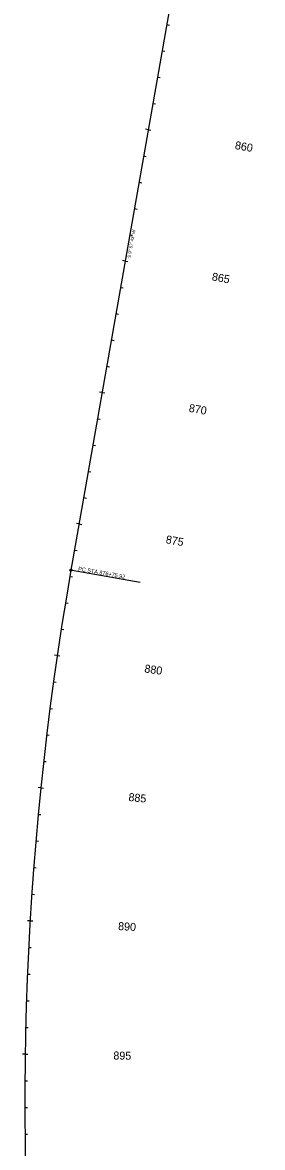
# Model space of a CAD drawing. Extents: x 2820825 to 2825694, y 116785 to 142398.
# Drawn here: x 2820825 to 2821726, y 129646 to 133862 of the extents above; entities that cross this region are included whole.
import ezdxf

# ---------------------------------------------------------------- set-up
doc = ezdxf.new("R2010")
doc.units = 0
for name, color, linetype in [('Default', 7, 'Continuous'), ('Roadway-Centerline main', 7, 'Continuous'), ('Roadway-Curve pc pt', 7, 'Continuous'), ('Text-Alignment info', 7, 'Continuous')]:
    doc.layers.add(name, color=color, linetype=linetype)

msp = doc.modelspace()

# ---------------------------------------------------------------- linework, layer by layer
at = {"layer": 'Default'}
msp.add_line((2821447.5, 134317.2), (2821007.1, 131809.7), dxfattribs=at)
msp.add_arc((2832333.7, 129820.2), 11500, 170.03806, 202.7163, dxfattribs=at)
at = {"layer": 'Roadway-Centerline main'}
for p, q in [((2821447.5, 134317.2), (2821007.1, 131809.7)), ((2821366.2, 133854.3), (2821376.1, 133852.6)), ((2821348.9, 133755.8), (2821358.8, 133754.1)), ((2821331.6, 133657.3), (2821341.5, 133655.6)), ((2821314.3, 133558.8), (2821324.2, 133557.1)), ((2821297, 133460.3), (2821287.2, 133462.1)), ((2821297, 133460.3), (2821306.9, 133458.6)), ((2821279.7, 133361.8), (2821289.6, 133360.1)), ((2821262.4, 133263.3), (2821272.3, 133261.6)), ((2821245.1, 133164.8), (2821255, 133163.1)), ((2821227.8, 133066.4), (2821237.7, 133064.6)), ((2821210.5, 132967.9), (2821200.7, 132969.6)), ((2821210.5, 132967.9), (2821220.4, 132966.1)), ((2821193.2, 132869.4), (2821203.1, 132867.6)), ((2821175.9, 132770.9), (2821185.8, 132769.2)), ((2821158.6, 132672.4), (2821168.5, 132670.7)), ((2821141.3, 132573.9), (2821151.2, 132572.2)), ((2821124, 132475.4), (2821114.2, 132477.1)), ((2821124, 132475.4), (2821133.9, 132473.7)), ((2821106.7, 132376.9), (2821116.6, 132375.2)), ((2821089.4, 132278.4), (2821099.3, 132276.7)), ((2821072.1, 132179.9), (2821082, 132178.2)), ((2821054.8, 132081.4), (2821064.7, 132079.7)), ((2821037.5, 131982.9), (2821027.7, 131984.7)), ((2821037.5, 131982.9), (2821047.4, 131981.2)), ((2821020.2, 131884.5), (2821030.1, 131882.7)), ((2821002.9, 131786), (2821012.8, 131784.2)), ((2820986.3, 131687.4), (2820996.1, 131685.7)), ((2820970.5, 131588.6), (2820980.3, 131587.1)), ((2820955.5, 131489.7), (2820945.6, 131491.2)), ((2820955.5, 131489.7), (2820965.4, 131488.3)), ((2820941.4, 131390.7), (2820951.3, 131389.4)), ((2820928.2, 131291.6), (2820938.1, 131290.3)), ((2820915.8, 131192.4), (2820925.8, 131191.2)), ((2820904.3, 131093), (2820914.3, 131091.9)), ((2820893.7, 130993.6), (2820883.8, 130994.6)), ((2820893.7, 130993.6), (2820903.7, 130992.6)), ((2820883.9, 130894.1), (2820893.9, 130893.2)), ((2820875, 130794.5), (2820885, 130793.6)), ((2820867, 130694.8), (2820877, 130694)), ((2820859.8, 130595.1), (2820869.8, 130594.4)), ((2820853.5, 130495.3), (2820843.5, 130495.9)), ((2820853.5, 130495.3), (2820863.5, 130494.7)), ((2820848.1, 130395.4), (2820858.1, 130394.9)), ((2820843.5, 130295.5), (2820853.5, 130295.1)), ((2820839.8, 130195.6), (2820849.8, 130195.3)), ((2820837, 130095.6), (2820847, 130095.4)), ((2820835, 129995.6), (2820825, 129995.8)), ((2820835, 129995.6), (2820845, 129995.5)), ((2820833.9, 129895.7), (2820843.9, 129895.6)), ((2820833.7, 129795.7), (2820843.7, 129795.7)), ((2820834.4, 129695.7), (2820844.4, 129695.8))]:
    msp.add_line(p, q, dxfattribs=at)
msp.add_arc((2832333.7, 129820.2), 11500, 170.03806, 202.7163, dxfattribs=at)
at = {"layer": 'Roadway-Curve pc pt'}
msp.add_line((2821011, 131809), (2821266.9, 131764), dxfattribs=at)
msp.add_circle((2821007.1, 131809.7), 4, dxfattribs=at)

# ---------------------------------------------------------------- texts
at = {"layer": 'Roadway-Centerline main'}
for s, rotation, p in [(' 860', 350.0381, (2821609.6, 133390.2)), (' 865', 350.0381, (2821523.1, 132897.7)), (' 870', 350.0381, (2821436.6, 132405.3)), (' 875', 350.0381, (2821350.1, 131912.8)), (' 880', 351.6527, (2821270, 131428.4)), (' 885', 354.1438, (2821210.5, 130946)), (' 890', 356.635, (2821172.1, 130461.5)), (' 895', 359.1261, (2821154.8, 129975.8))]:
    msp.add_text(s, height=30, rotation=rotation, dxfattribs=at).set_placement(p)
at = {"layer": 'Roadway-Curve pc pt'}
msp.add_text('PC STA 876+75.92', height=15, rotation=350.0381, dxfattribs=at).set_placement((2821033.2, 131808.1))
at = {"layer": 'Text-Alignment info'}
msp.add_text('S 9%%d 57\' 43" W', height=12, rotation=80.0381, dxfattribs=at).set_placement((2821230.8, 132979.3))

doc.saveas('drawing.dxf')
